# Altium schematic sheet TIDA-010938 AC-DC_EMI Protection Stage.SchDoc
size 431 x 279 mm; Date: Not shown in title block; ApprovedBy: Not shown in title block; CheckedBy: Not shown in title block; Author: Not shown in title block; CompanyName: Not shown in title block; Engineer: Not shown in title block; Organization: Not shown in title block; Address1: Not shown in title block; Address2: Not shown in title block; Address3: Not shown in title block; Address4: Not shown in title block; DocumentNumber: 5; Revision: Use project parameter SCH_Rev; SheetNumber: 6; SheetTotal: 11; PageSetup: Record=PageOptions¦CenterHorizontal=True¦CenterVertical=True¦PrintScale=1.00¦XCorrection=1.00¦YCorrection=1.00¦PrintKind=0¦BorderSize=5000000¦LeftOffset=0¦BottomOffset=0¦Orientation=2¦PaperLength=1000¦PaperWidth=1000¦Scale=100¦PaperSource=15¦PrintQuality=600¦MediaType=1¦DitherType=10¦PaperKind=Letter¦PrintScaleMode=1
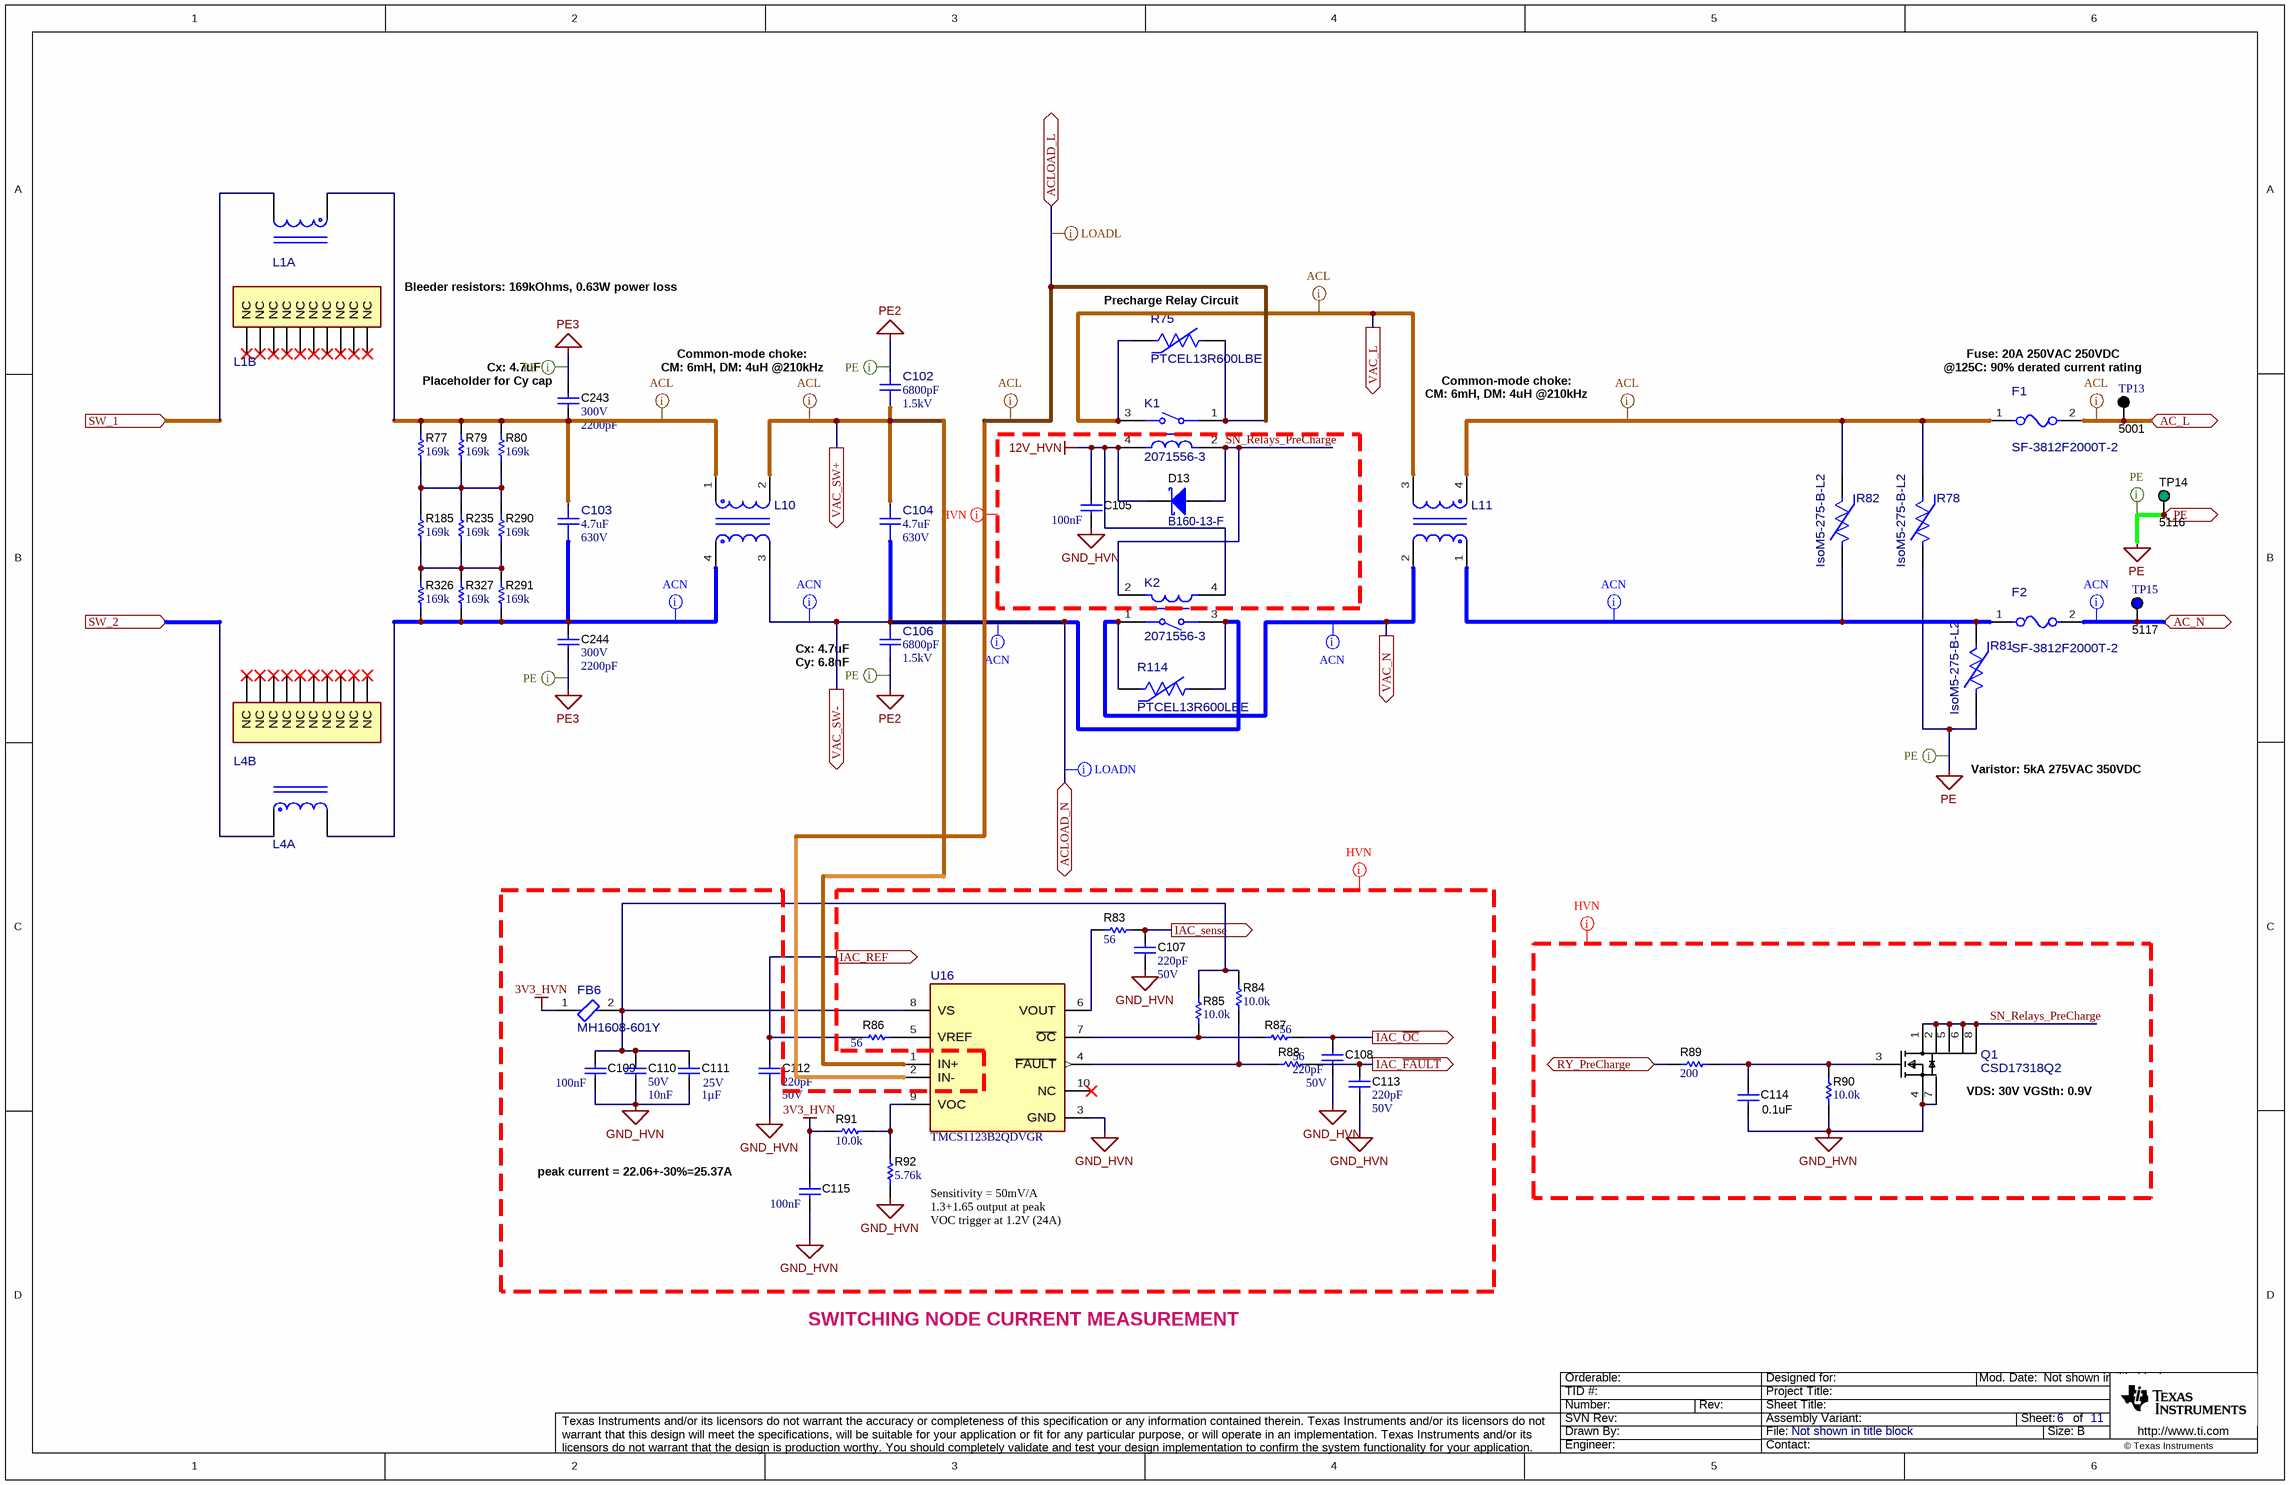
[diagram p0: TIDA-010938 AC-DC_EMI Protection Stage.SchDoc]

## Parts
C102  ValueDisplayed: 6800pF  VDC_V: 1.5kV  [FP-R413F168050T0K_RADIAL-MFG]  (hidden comment: R413F168050T0K)
C103  ValueDisplayed: 4.7uF  VDC_V: 630V  [FP-F862FY475K310ZV054_RADIAL-MFG]  (hidden comment: F862FY475K310ZV054)
C104  ValueDisplayed: 4.7uF  VDC_V: 630V  [FP-F862FY475K310ZV054_RADIAL-MFG]  (hidden comment: F862FY475K310ZV054)
C105  Cap_F: 100nF  [0603]  (hidden comment: GRM188R72A104KA35J)
C106  ValueDisplayed: 6800pF  VDC_V: 1.5kV  [FP-R413F168050T0K_RADIAL-MFG]  (hidden comment: R413F168050T0K)
C107  Cap_F: 220pF  VDC_V: 50V  [0603]  (hidden comment: GRM188R71H221KA01D)
C108  Cap_F: 220pF  VDC_V: 50V  [0603]  (hidden comment: GRM188R71H221KA01D)
C109  Cap_F: 100nF  [0603]  (hidden comment: GRM188R72A104KA35J)
C110  VDC_V: 50V  Cap_F: 10nF  [0603]  (hidden comment: 885012206089)
C111  VDC_V: 25V  ValueDisplayed: 1µF  [0603]  (hidden comment: TMK107BJ105KA-T)
C112  Cap_F: 220pF  VDC_V: 50V  [0603]  (hidden comment: GRM188R71H221KA01D)
C113  Cap_F: 220pF  VDC_V: 50V  [0603]  (hidden comment: GRM188R71H221KA01D)
C114  ValueDisplayed: 0.1uF  [0603]  (hidden comment: 885012206095)
C115  Cap_F: 100nF  [0603]  (hidden comment: GRM188R72A104KA35J)
C243  VDC_V: 300V  ValueDisplayed: 2200pF  [E_900x700x900]  (hidden comment: DE6E3KJ222MN3A)
C244  VDC_V: 300V  ValueDisplayed: 2200pF  [E_900x700x900]  (hidden comment: DE6E3KJ222MN3A)
D13  B160-13-F  [SMA]
F1  SF-3812F2000T-2  [FP-SF-3812F2000T-2_3812-MFG]
F2  SF-3812F2000T-2  [FP-SF-3812F2000T-2_3812-MFG]
FB6  MH1608-601Y  [FP-MH1608-601Y_0603-MFG]
K1  2071556-3  [FP-2071556-3_PTH_RELAY_18MM2_10MM2-MFG]
K2  2071556-3  [FP-2071556-3_PTH_RELAY_18MM2_10MM2-MFG]
L1  B180990  [FP-B180990_PTH12_39MM8_41MM4-MFG]  (value not drawn)  (parts A,B of 2)
L4  B180990  [FP-B180990_PTH12_39MM8_41MM4-MFG]  (value not drawn)  (parts A,B of 2)
L10  D6744  [FP-D6744_PTH_CMC_38MM0-MFG]  (value not drawn)
L11  D6744  [FP-D6744_PTH_CMC_38MM0-MFG]  (value not drawn)
Q1  CSD17318Q2  [FP-CSD17318Q2_WSON6-MFG]
R75  PTCEL13R600LBE  [FP-PTCEL13R600LBE_RADIAL-MFG]
R77  ValueDisplayed: 169k  [1206]  (hidden comment: ERJ-8ENF1693V)
R78  IsoM5-275-B-L2  [FP-IsoM5-275-B-L2_RADIAL-MFG]
R79  ValueDisplayed: 169k  [1206]  (hidden comment: ERJ-8ENF1693V)
R80  ValueDisplayed: 169k  [1206]  (hidden comment: ERJ-8ENF1693V)
R81  IsoM5-275-B-L2  [FP-IsoM5-275-B-L2_RADIAL-MFG]
R82  IsoM5-275-B-L2  [FP-IsoM5-275-B-L2_RADIAL-MFG]
R83  ValueDisplayed: 56  [0603]  (hidden comment: RG1608P-560-B-T5)
R84  ValueDisplayed: 10.0k  [0603]  (hidden comment: RG1608P-103-B-T5)
R85  ValueDisplayed: 10.0k  [0603]  (hidden comment: RG1608P-103-B-T5)
R86  ValueDisplayed: 56  [0603]  (hidden comment: RG1608P-560-B-T5)
R87  ValueDisplayed: 56  [0603]  (hidden comment: RG1608P-560-B-T5)
R88  ValueDisplayed: 56  [0603]  (hidden comment: RG1608P-560-B-T5)
R89  ValueDisplayed: 200  [0603]  (hidden comment: RT0603DRE07200RL)
R90  ValueDisplayed: 10.0k  [0603]  (hidden comment: RG1608P-103-B-T5)
R91  ValueDisplayed: 10.0k  [0603]  (hidden comment: RG1608P-103-B-T5)
R92  ValueDisplayed: 5.76k  [0603]  (hidden comment: RT0603DRE075K76L)
R114  PTCEL13R600LBE  [FP-PTCEL13R600LBE_RADIAL-MFG]
R185  ValueDisplayed: 169k  [1206]  (hidden comment: ERJ-8ENF1693V)
R235  ValueDisplayed: 169k  [1206]  (hidden comment: ERJ-8ENF1693V)
R290  ValueDisplayed: 169k  [1206]  (hidden comment: ERJ-8ENF1693V)
R291  ValueDisplayed: 169k  [1206]  (hidden comment: ERJ-8ENF1693V)
R326  ValueDisplayed: 169k  [1206]  (hidden comment: ERJ-8ENF1693V)
R327  ValueDisplayed: 169k  [1206]  (hidden comment: ERJ-8ENF1693V)
TP13  5001  [Keystone5001]
TP14  5116  [Keystone_5116]
TP15  5117  [Keystone5117]
U16  TMCS1123B2QDVGR  [DVG0010A-MFG]

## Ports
AC_L (bidir), AC_N (bidir), ACLOAD_L (bidir), ACLOAD_N (bidir), IAC_REF (out), IAC_sense (out), IAC_~{FAULT} (out), IAC_~{OC} (out), PE (bidir), RY_PreCharge (bidir), SW_1 (in), SW_2 (in), VAC_L (out), VAC_N (out), VAC_SW+ (out), VAC_SW- (out)

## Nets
3V3_HVN: C115.1 FB6.1 R91.1
12V_HVN: C105.1 D13.1(K) K1.4 K2.4
GND_HVN: C105.2 C107.1 C108.1 C109.2 C110.2 C111.2 C112.1 C113.1 C114.2 C115.2 Q1.4(S) Q1.7(S) R90.2 R92.1 U16.3(GND)
PE: R78.1 R81.1 TP14.1 ; port PE
PE2: C102.2 C106.1
PE3: C243.1 C244.2
AC_L: F1.2 TP13.1 ; port AC_L
AC_N: F2.2 TP15.1 ; port AC_N
ACLOAD_L: K1.1 R75.2 U16.2(IN-) ; port ACLOAD_L
ACLOAD_N: C104.1 C106.2 K2.3 L10.3 R114.2 ; port VAC_SW-, port ACLOAD_N
IAC_~{FAULT}: C113.2 R88.2 ; port IAC_~{FAULT}
IAC_~{OC}: C108.2 R87.2 ; port IAC_~{OC}
IAC_REF: C112.2 R86.1 ; port IAC_REF
IAC_sense: C107.2 R83.2 ; port IAC_sense
RY_PreCharge: R89.1 ; port RY_PreCharge
SN_Relays_PreCharge: D13.2(A) K1.2 K2.2 Q1.1(D) Q1.2(D) Q1.5(D) Q1.6(D) Q1.8(D)
SW_1: L1.6 ; port SW_1
SW_2: L4.1 ; port SW_2
VAC_L: K1.3 L11.3 R75.1 ; port VAC_L
VAC_N: K2.1 L11.2 R114.1 ; port VAC_N
VAC_SW+: C102.1 C104.2 L10.2 U16.1(IN+) ; port VAC_SW+
NetC103_1: C103.1 C244.1 L4.6 L10.4 R291.1 R326.1 R327.1
NetC103_2: C103.2 C243.2 L1.1 L10.1 R77.2 R79.2 R80.2
NetC109_1: C109.1 C110.1 C111.1 FB6.2 R84.1 R85.1 U16.8(VS)
NetC114_1: C114.1 Q1.3(G) R89.2 R90.1
NetF1_1: F1.1 L11.4 R78.2 R82.2
NetF2_1: F2.1 L11.1 R81.2 R82.1
NetR77_1: R77.1 R79.1 R80.1 R185.2 R235.2 R290.2
NetR83_1: R83.1 U16.6(VOUT)
NetR84_2: R84.2 R88.1 U16.4(~{FAULT})
NetR85_2: R85.2 R87.1 U16.7(~{OC})
NetR86_2: R86.2 U16.5(VREF)
NetR91_2: R91.2 R92.2 U16.9(VOC)
NetR185_1: R185.1 R235.1 R290.1 R291.2 R326.2 R327.2

Not connected (* = marked no-connect by the designer): L1 2(NC)* 3(NC)* 4(NC)* 5(NC)* 7(NC)* 8(NC)* 9(NC)* 10(NC)* 11(NC)* 12(NC)*; L4 2(NC)* 3(NC)* 4(NC)* 5(NC)* 7(NC)* 8(NC)* 9(NC)* 10(NC)* 11(NC)* 12(NC)*; U16 10(NC)*

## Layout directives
net class HVN: 3V3_HVN, 12V_HVN, GND_HVN, SN_Relays_PreCharge
net class ACL: AC_L, ACLOAD_L, NetC103_2, NetF1_1, VAC_L, VAC_SW+
net class ACN: AC_N, ACLOAD_N, NetC103_1, NetF2_1, VAC_N
net class PE: PE, PE2, PE3
net class LOADL: ACLOAD_L

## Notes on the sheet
- (near L1) Bleeder resistors: 169kOhms, 0.63W power loss
- (near R75) Precharge Relay Circuit
- (near C243) Cx: 4.7uF
- Common-mode choke:
- CM: 6mH, DM: 4uH @210kHz
- Fuse: 20A 250VAC 250VDC
- @125C: 90% derated current rating
- (near C243) Placeholder for Cy cap
- (near C106) Cx: 4.7uF
- (near C106) Cy: 6.8nF
- Varistor: 5kA 275VAC 350VDC
- (near Q1) VDS: 30V VGSth: 0.9V
- peak current = 22.06+-30%=25.37A
- (near R92) Sensitivity = 50mV/A
  1.3+1.65 output at peak
  VOC trigger at 1.2V (24A)
- SWITCHING NODE CURRENT MEASUREMENT

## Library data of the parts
C102 C106 = CMP-0042924-1: 6800 pF Film Capacitor 300V 1500V (1.5kV) Polypropylene (PP), Metallized Radial; Manufacturer: KEMET; AEC Grade: Grade 1; AEC Qualified: Yes; Cap_F: 6.8nF; SizeZ_mm: 12.1mm; Tolerance_%: 10%; VAC_Y: Y2; Value: 6.8nF
C103 C104 = CMP-0038396-1: 4.7 µF Film Capacitor 310V 630V Polypropylene (PP), Metallized Radial; Manufacturer: KEMET; AEC Grade: Grade 2; AEC Qualified: Yes; Cap_F: 4.7µF; SizeZ_mm: 37mm; Tolerance_%: 10%; VAC_X: X2; Value: 4.7µF
C105 C109 C115 = CMP-0007470-5: CAP, CERM, 0.1 uF, 100 V, +/- 10%, X7R, 0603; Manufacturer: MuRata; TaMin_C: -55°C; Polarized: N; SizeAreaWB_mm2: 4.68; Value1: Unknown; U/M: EA; Value: 0.1uF; TaMax_C: 125°C; SizeZ_mm: 1; SizeX_mm: 1.6; SizeY_mm: 0.8; Value2: 100V; SizeArea_mm2: 1.28; AEC Category: Q200
C107 C108 C112 C113 = CMP-0007442-5: CAP, CERM, 220 pF, 50 V, +/- 10%, X7R, 0603; Manufacturer: MuRata; TaMin_C: -55°C; Polarized: N; SizeAreaWB_mm2: 4.68; Value1: Unknown; U/M: EA; Value: 220pF; TaMax_C: 125°C; SizeZ_mm: 1; SizeX_mm: 1.6; SizeY_mm: 0.8; SizeArea_mm2: 1.28; AEC Category: Q200
C110 = CMP-0750039-1: CAP, CERM, 0.01 µF, 50 V,+/- 10%, X7R, 0603; Manufacturer: Wurth Elektronik; Polarized: N; AEC Category: Q200; TaMax_C: 125°C; SizeAreaWB_mm2: 4.68; Value: 0.01uF; SizeArea_mm2: 1.28; SizeY_mm: 0.8; SizeZ_mm: 1; ValueDisplayed: 0.01µF; SizeX_mm: 1.6; U/M: EA; TaMin_C: -55°C
C111 = CMP-0086152-1: CAP, CERM, 1 µF, 25 V,+/- 10%, X5R, 0603; Manufacturer: Taiyo Yuden; SizeAreaWB_mm2: 4.68; SizeZ_mm: 1; U/M: EA; Green_REACh: Passed; Value: 1uF; AEC Qualified: N; TaMax_C: 85°C; Green_Lifecycle: Active; AEC Category: Q200; SizeArea_mm2: 1.28; TaMin_C: -55°C; SizeY_mm: 0.8; SizeX_mm: 1.6
C114 = CMP-0006837-4: CAP, CERM, 0.1 uF, 50 V, +/- 10%, X7R, 0603; Manufacturer: Wurth Elektronik; TaMin_C: -55°C; Polarized: N; SizeAreaWB_mm2: 4.68; Value1: Unknown; U/M: EA; Value: 0.1uF; TaMax_C: 125°C; SizeZ_mm: 1; SizeX_mm: 1.6; SizeY_mm: 0.8; Value2: 50V; SizeArea_mm2: 1.28; CompType: Capacitor; Cap_F: 100nF; AEC Category: Q200
C243 C244 = CMP-0009613-2: CAP, CERM, 2200 pF, 300 V, +/- 20%, E, TH, 2- Leads, Body 9x7mm, Pin Spacing 7.5mm; Manufacturer: MuRata; TaMin_C: -40°C; Polarized: N; SizeAreaWB_mm2: 99; Value1: Unknown; U/M: EA; Value: 2200pF; TaMax_C: 125°C; SizeZ_mm: 12; SizeX_mm: 9; SizeY_mm: 7; Cap_Case: 9x7x9mm; SizeArea_mm2: 63; Cap_F: 2.2nF; AEC Category: Q200
D13 = CMP-0028389-2: Diode, Schottky, 60 V, 1 A, SMA; Manufacturer: Diodes Inc.; Green_Lifecycle: Not Set; SizeAreaWB_mm2: 37.3428; Green_REACh: Incomplete; TJmax_C: 150°C; AEC Category: Q101; SizeZ_mm: 2.87; RJC_CperW: 20; Io_A: 1A; SizeArea_mm2: 16.3228; Vf_V: 700mV; Value2: 0.7V; SizeY_mm: 2.92; Vr_V: 60V; SizeX_mm: 5.59; Value: 60V
F1 F2 = CMP-0042962-1: 20 A 250 V AC 80 V DC Fuse Board Mount (Cartridge Style Excluded) Surface Mount 2-SMD, Square End Block; Manufacturer: Bourns; Interrupt_AC: 150A; Interrupt_DC: 300A; MeltingTyp: 356A2Sec; SizeZ_mm: 3.3mm; VAC_V: 250V; Fuse Speed: Fast; AEC Qualified: No; Fuse Current: 20A; Res_ohm: 0.003Ω
FB6 = CMP-0037505-1: 600 Ohms @ 100 MHz 1 Power, Signal Line Ferrite Bead 0603 (1608 Metric) 1A 200mOhm; Manufacturer: Bourns; DCR_ohm: 0.2; SizeZ_mm: 1mm; AEC Qualified: No; Impedance At Frequency: 600Ω @ 100MHz; Test Frequency: 100MHz; Tolerance_%: 25%
K1 K2 = CMP-0042926-1: General Purpose Relay SPST-NO (1 Form A) 12VDC Coil Through Hole; Manufacturer: TE Connectivity; Coil Power_W: 450mW; Coil Type: Non-Latching; Coil Voltage_VDC: 12V; Contact Rating_A: 16A; SizeZ_mm: 15.3mm; AEC Qualified: No; Coil Resistance: 320Ω; TaMax_C: +85°C; TaMin_C: -40°C
L1 L4 = CMP-0048794-1: Inductor 95.16 µH; Manufacturer: Bourns; AEC Qualified: No; SizeZ_mm: 42.5mm; Value: 95.16uH; Test Frequency: 100Hz
L10 L11 = CMP-0042320-3: Common Mode Chokes 4mH 50mohm 250kHz; Manufacturer: Bourns; AEC Qualified: No; DCR_ohm: 50m; SizeZ_mm: 24mm
Q1 = CMP-0076725-1: 30-V N-Channel NexFET™ Power MOSFET; Manufacturer: Texas Instruments; VdsMax_V: 30V; SizeZ_mm: 0.8mm; ChMode: False; QgTyp_nC: 6nC @ 4.5V; Rdson45_ohm: 0.0139; Vgs_V: 10V; AEC Qualified: No; IdsMax_A: 10A
R75 R114 = CMP-0097004-1: PTCEL Series 500 V 60 Ohm ±30 % Radial Inrush Current Limiter PTC Thermistor; Manufacturer: Vishay Bccomponents; Value: 60Ω; SizeZ_mm: 17mm; AEC Qualified: Yes; Hold Current: 120mA; Tolerance_%: 30%; VDC_V: 500V; AEC Grade: Grade 2
R77 R79 R80 R185 R235 R290 R291 R326 R327 = CMP-0017399-3: RES, 169 k, 1%, 0.25 W, AEC-Q200 Grade 0, 1206; Manufacturer: Panasonic; Power_W: 250mW; TempCo: 100 ppm/C; Value: 169k; EIA_Code: E96; SizeX_mm: 3.2; SizeY_mm: 1.6; SizeZ_mm: 1.35; Value2: 0.25W; SizeArea_mm2: 5.12; AEC Qualified: Y; VDC_V: 200V; AEC Category: Q200; AEC Grade: 0; SizeAreaWB_mm2: 10.92
R78 R81 R82 = CMP-0096768-1: 5 kA Varistor 1 Circuit Through Hole Disc 17mm; Manufacturer: Bourns; AEC Qualified: No; SizeZ_mm: 23mm; VDC_V: 350V; Vc: 100A; ValueDisplayed: 40pF; Clamping Voltage: 730V
R83 R86-R88 = CMP-0023572-3: RES, 56, 0.1%, 0.1 W, 0603; Manufacturer: Susumu Co Ltd; Power_W: 100mW; TempCo: 25 ppm/C; Value_Code: 56R0; U/M: EA; Value: 56; SizeX_mm: 1.6; SizeY_mm: 0.8; SizeZ_mm: 1; Value2: 0.1W; SizeArea_mm2: 1.28; VDC_V: 75V; AEC Category: Q200
R84 R85 R90 R91 = CMP-0023404-1: RES, 10.0 k, 0.1%, 0.1 W, 0603; Manufacturer: Susumu Co Ltd; Power_W: 100mW; TempCo: 25 ppm/C; Value_Code: 10k0; U/M: EA; Value: 10.0k; EIA_Code: E192; Res_ohm: 10k; SizeX_mm: 1.6; SizeY_mm: 0.8; SizeZ_mm: 1; Value2: 0.1W; SizeArea_mm2: 1.28; VDC_V: 75V; AEC Category: Q200
R89 = CMP-0024912-2: RES, 200, 0.5%, 0.1 W, 0603; Manufacturer: Yageo America; Power_W: 100mW; TempCo: 50 ppm/C; Value_Code: 200R; U/M: EA; Value: 200; EIA_Code: E192; SizeX_mm: 1.6; SizeY_mm: 0.8; SizeZ_mm: 1; Value2: 0.1W; SizeArea_mm2: 1.28; VDC_V: 75V; AEC Category: Q200
R92 = CMP-0025444-3: RES, 5.76 k, 0.5%, 0.1 W, 0603; Manufacturer: Yageo America; Power_W: 100mW; TempCo: 50 ppm/C; Value_Code: 5k76; U/M: EA; Value: 5.76k; EIA_Code: E192; SizeX_mm: 1.6; SizeY_mm: 0.8; SizeZ_mm: 1; Value2: 0.1W; SizeArea_mm2: 1.28; VDC_V: 75V; AEC Category: Q200
TP13 = CMP-0055138-2: Test Point, Miniature, Black, TH; Manufacturer: Keystone Electronics; ContactFinish: Silver; CNHeader: FALSE; Green_Lifecycle: Active; Green_REACh: Passed; CT: TRUE
TP14 = CMP-0055164-1: Test Point, Miniature, Green, TH; Manufacturer: Keystone; CNHeader: FALSE; Green_Lifecycle: Active; Green_REACh: Passed; Row_Count: 1; ContactFinish: Silver; CT: TRUE; Cert_UL: Y
TP15 = CMP-0055154-1: Test Point, Miniature, Blue, TH; Manufacturer: Keystone; CNHeader: FALSE; Green_Lifecycle: Active; Green_REACh: Passed; ContactFinish: Silver; CT: TRUE
U16 = CMP-0096052-1: Manufacturer: Texas Instruments; Standoff Height: 0.1mm; SizeZ_mm: 2.65mm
